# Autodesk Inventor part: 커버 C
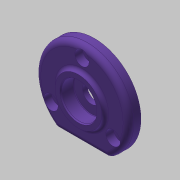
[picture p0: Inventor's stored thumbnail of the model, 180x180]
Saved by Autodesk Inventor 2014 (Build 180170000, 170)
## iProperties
Created: 2020-04
Part Number: 커버 C
Material: 알루미늄 6061
Document SubType Name: Modeling
Designer: mduedu
Density: 2.71 g/cm^3
Appearance: 보라색
Mass: 35.2376 g
Surface Area: 62.3739 cm^2
Volume: 13.0028 cm^3
Author: mduedu
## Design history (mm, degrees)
sketch "스케치1"
  geometry: C1 r 26 at (0, 0); 1 further point
  constraints: 1 centre point, 1 coincident
  dimensions: "d0" = 52 diameter of C1
extrude "돌출1" new body sketch "스케치1" distance "d1" = 7; taper "d2" = 0 deg
sketch "스케치2"
  geometry: L1 (-14.62, -21.5)-(14.62, -21.5); A1 r 26 centre (0, 0) between (-14.62, -21.5) and (14.62, -21.5) reference; 1 further point
  constraints: 2 end point, 2 point on circle, 1 horizontal
  dimensions: "d3" = 21.5 distance from line of L1 point (0, 0)
extrude "돌출2" cut sketch "스케치2" stored distance "d4" = 7; taper "d5" = 0 deg
sketch "스케치6"
  geometry: C1 r 13 at (0, 0); 1 further point
  constraints: 1 centre point, 1 coincident
  dimensions: "d29" = 26 diameter of C1
extrude "돌출5" join sketch "스케치6" distance "d30" = 2; taper "d31" = 0 deg
fillet "모깎기1" dims "d6" = 3
fillet "모깎기2" dims "d7" = 3
fillet "모깎기4" dims "d33" = 2
sketch "스케치3" dims "d8" = 40
  geometry: 3 further points
  constraints: 2 vertical alignment, 1 coincident, 2 other
hole "구멍1" sketch "스케치3" at (0, 20) diameter "d9" = 4.5; stored, may be unused: countersink angle "d13" = 90 deg, drill point angle "d15" = 118 deg; dims "d10" = 6, "d11" = 8, "d12" = 4.4, "d14" = 8
sketch "스케치4"
  geometry: C1 r 14 at (0, 0); 1 further point
  constraints: 1 centre point, 1 coincident
  dimensions: "d19" = 28 diameter of C1
extrude "돌출3" join sketch "스케치4" distance "d20" = 4; taper "d21" = 0 deg
sketch "스케치5"
  geometry: C1 r 12 at (0, 0); 1 further point
  constraints: 1 centre point, 1 coincident
  dimensions: "d22" = 24 diameter of C1
extrude "돌출4" cut sketch "스케치5" distance "d23" = 3; taper "d24" = 0 deg
fillet "모깎기3" dims "d25" = 3
chamfer "모따기1" distance "d26" = 0.5; stored, may be unused: second distance "d27" = 2, angle "d28" = 45 deg
sketch "스케치7"
  geometry: 2 further points
  constraints: 1 coincident
hole "구멍2" sketch "스케치7" at (0, 0) diameter "d34" = 10; stored, may be unused: countersink angle "d38" = 90 deg, drill point angle "d40" = 118 deg; dims "d35" = 6, "d36" = 20, "d37" = 7.3, "d39" = 8
fillet "모깎기5" dims "d41" = 0.3
chamfer "모따기2" distance "d42" = 0.7; stored, may be unused: second distance "d43" = 2, angle "d44" = 30 deg
node "솔리드1"
pattern_circular "원형 패턴1" dims angle "d17" = 360 deg
node "투영된 루프1"
